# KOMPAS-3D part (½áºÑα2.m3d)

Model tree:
1. Эскиз:1
2. Операция выдавливания:1
     Расстояние 1 = 7
3. Эскиз:20
4. Операция выдавливания:17
     Расстояние 1 = 0.3; Расстояние 2 = 7.3
5. Эскиз:22
6. Вырезать элемент выдавливания:3
     Расстояние 1 = 14.287
7. Эскиз:23
8. Операция выдавливания:18
     Расстояние 1 = 0.3; Расстояние 2 = 7.3
9. Эскиз:24
10. Операция выдавливания:19
     Расстояние 1 = 0.1; Расстояние 2 = 7.3
11. Эскиз:25
12. Операция выдавливания:20
     Расстояние 1 = 0.1; Расстояние 2 = 7.3
13. Эскиз:26
14. Вырезать элемент выдавливания:4
     Расстояние 1 = 0.1
15. Эскиз:27
16. Операция выдавливания:21
     Расстояние 1 = 1; Расстояние 2 = 2.7
17. Эскиз:28
18. Операция выдавливания:22
     Расстояние 1 = 0.1; Расстояние 2 = 1.7
19. Эскиз:29
20. Операция выдавливания:23
     Расстояние 1 = 0.5; Расстояние 2 = 1
21. Эскиз:30
22. Операция выдавливания:24
     Расстояние 1 = 5; Расстояние 2 = 1
23. Эскиз:31
24. Операция выдавливания:25
     Расстояние 1 = 0.3; Расстояние 2 = 1
25. Эскиз:32
26. Вырезать элемент выдавливания:5
     Расстояние 1 = 0.5
27. Скругление:27
     Радиус = 0.2
28. Скругление:28
     Радиус = 0.2
29. Зеркальный массив:4  (with: Операция выдавливания:1, Операция выдавливания:17, Вырезать элемент выдавливания:3, Операция выдавливания:18, Операция выдавливания:19, Операция выдавливания:20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)  (labels: Экземпляр ( 1 ); Экземпляр ( 2 ))
30. Скругление:29
     Радиус = 0.2
31. Скругление:30
     Радиус = 0.2
32. Эскиз:33
33. Вырезать элемент выдавливания:6
     Расстояние 1 = 7.3
34. Скругление:31
     Радиус = 1
35. Скругление:32
     Радиус = 0.5
36. Эскиз:34
37. Операция выдавливания:26
     Расстояние 1 = 0.3; Расстояние 2 = 1
38. Скругление:33
     Радиус = 0.1
39. Эскиз:35
40. Вырезать элемент выдавливания:7
     Расстояние 1 = 0.1

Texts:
  лазер2
  Сплав АЛ8  ГОСТ 1583-93
  Экземпляр ( 1 )
  Экземпляр ( 2 )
